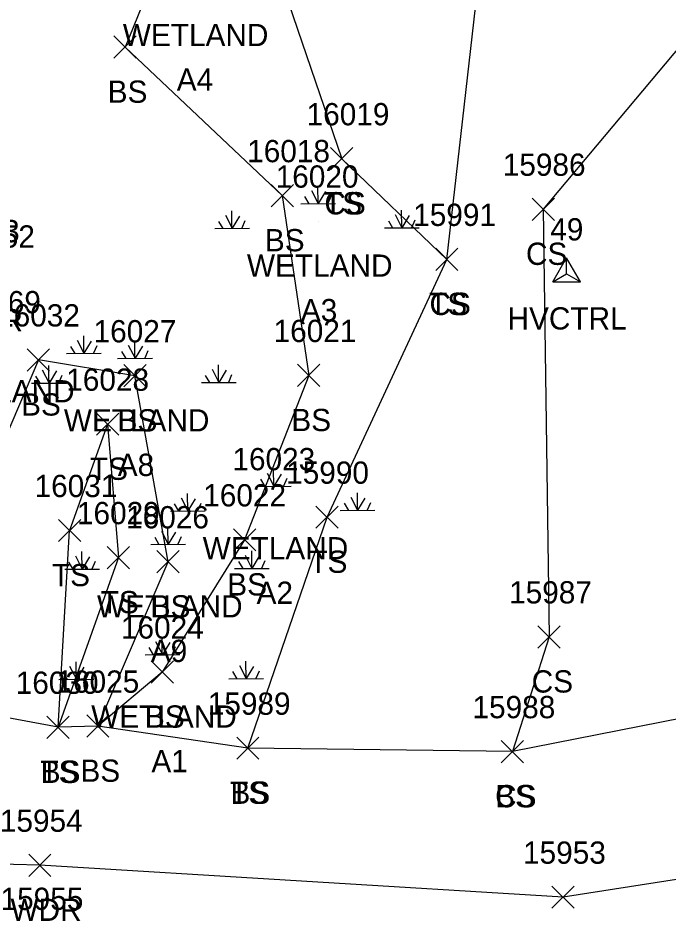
# Model space of a CAD drawing. Extents: x 1606530 to 1613020, y 784959 to 789666.
# Drawn here: x 1609329.8 to 1609388.2, y 788467.6 to 788548 of the extents above; entities that cross this region are included whole.
import ezdxf

# ---------------------------------------------------------------- set-up
doc = ezdxf.new("R2010")
doc.units = 0
for name, color, linetype in [('C_A', 7, 'Continuous'), ('C_I', 7, 'Continuous'), ('CPSM', 7, 'Continuous'), ('L_A', 7, 'Continuous'), ('L_C', 7, 'Continuous'), ('L_I', 7, 'Continuous'), ('L_TIC', 7, 'Continuous'), ('LAWA', 7, 'Continuous'), ('LELB', 7, 'Continuous'), ('LWET', 7, 'Continuous')]:
    doc.layers.add(name, color=color, linetype=linetype)

msp = doc.modelspace()

# ---------------------------------------------------------------- linework, layer by layer
at = {"layer": 'CPSM'}
for p, q in [((1609377.817, 788524.331), (1609379.067, 788526.496)), ((1609380.317, 788524.331), (1609379.067, 788526.496)), ((1609379.067, 788525.052), (1609379.067, 788526.496)), ((1609377.817, 788524.331), (1609379.067, 788525.052)), ((1609379.067, 788525.052), (1609379.067, 788525.052)), ((1609379.067, 788525.052), (1609380.317, 788524.331)), ((1609377.817, 788524.331), (1609380.317, 788524.331))]:
    msp.add_line(p, q, dxfattribs=at)
at = {"layer": 'L_TIC'}
for points in [[(1609338.409, 788544.413), (1609340.409, 788546.413)], [(1609340.409, 788544.413), (1609338.409, 788546.413)], [(1609357.873, 788534.391), (1609359.873, 788536.391)], [(1609359.873, 788534.391), (1609357.873, 788536.391)], [(1609357.873, 788534.391), (1609359.873, 788536.391)], [(1609359.873, 788534.391), (1609357.873, 788536.391)], [(1609352.526, 788531.076), (1609354.526, 788533.076)], [(1609354.526, 788531.076), (1609352.526, 788533.076)], [(1609375.975, 788529.856), (1609377.975, 788531.856)], [(1609377.975, 788529.856), (1609375.975, 788531.856)], [(1609367.309, 788525.354), (1609369.309, 788527.354)], [(1609369.309, 788525.354), (1609367.309, 788527.354)], [(1609367.309, 788525.354), (1609369.309, 788527.354)], [(1609369.309, 788525.354), (1609367.309, 788527.354)], [(1609330.632, 788516.324), (1609332.632, 788518.324)], [(1609332.632, 788516.324), (1609330.632, 788518.324)], [(1609339.298, 788514.898), (1609341.298, 788516.898)], [(1609341.298, 788514.898), (1609339.298, 788516.898)], [(1609354.901, 788514.928), (1609356.901, 788516.928)], [(1609356.901, 788514.928), (1609354.901, 788516.928)], [(1609336.843, 788510.551), (1609338.843, 788512.551)], [(1609338.843, 788510.551), (1609336.843, 788512.551)], [(1609336.843, 788510.551), (1609338.843, 788512.551)], [(1609338.843, 788510.551), (1609336.843, 788512.551)], [(1609356.552, 788502.201), (1609358.552, 788504.201)], [(1609358.552, 788502.201), (1609356.552, 788504.201)], [(1609333.433, 788501.004), (1609335.433, 788503.004)], [(1609335.433, 788501.004), (1609333.433, 788503.004)], [(1609333.433, 788501.004), (1609335.433, 788503.004)], [(1609335.433, 788501.004), (1609333.433, 788503.004)], [(1609349.146, 788500.166), (1609351.146, 788502.166)], [(1609351.146, 788500.166), (1609349.146, 788502.166)], [(1609337.811, 788498.568), (1609339.811, 788500.568)], [(1609339.811, 788498.568), (1609337.811, 788500.568)], [(1609342.274, 788498.194), (1609344.274, 788500.194)], [(1609344.274, 788498.194), (1609342.274, 788500.194)], [(1609376.491, 788491.451), (1609378.491, 788493.451)], [(1609378.491, 788491.451), (1609376.491, 788493.451)], [(1609341.753, 788488.296), (1609343.753, 788490.296)], [(1609343.753, 788488.296), (1609341.753, 788490.296)], [(1609332.393, 788483.335), (1609334.393, 788485.335)], [(1609334.393, 788483.335), (1609332.393, 788485.335)], [(1609332.393, 788483.335), (1609334.393, 788485.335)], [(1609334.393, 788483.335), (1609332.393, 788485.335)], [(1609335.962, 788483.436), (1609337.962, 788485.436)], [(1609337.962, 788483.436), (1609335.962, 788485.436)], [(1609335.962, 788483.436), (1609337.962, 788485.436)], [(1609337.962, 788483.436), (1609335.962, 788485.436)], [(1609349.434, 788481.457), (1609351.434, 788483.457)], [(1609351.434, 788481.457), (1609349.434, 788483.457)], [(1609349.434, 788481.457), (1609351.434, 788483.457)], [(1609351.434, 788481.457), (1609349.434, 788483.457)], [(1609373.203, 788481.146), (1609375.203, 788483.146)], [(1609375.203, 788481.146), (1609373.203, 788483.146)], [(1609373.203, 788481.146), (1609375.203, 788483.146)], [(1609375.203, 788481.146), (1609373.203, 788483.146)], [(1609330.758, 788470.946), (1609332.758, 788472.946)], [(1609332.758, 788470.946), (1609330.758, 788472.946)], [(1609377.742, 788468.077), (1609379.742, 788470.077)], [(1609379.742, 788468.077), (1609377.742, 788470.077)]]:
    msp.add_lwpolyline(points, dxfattribs=at)
at = {"layer": 'LAWA'}
msp.add_lwpolyline([(1609458.893, 788516.216), (1609465.518, 788489.735), (1609475.82, 788469.822), (1609458.93, 788473.776), (1609440.54, 788476.414), (1609422.319, 788472.182), (1609400.858, 788472.527), (1609378.742, 788469.077), (1609331.758, 788471.946), (1609305.698, 788472.619), (1609293.066, 788472.821), (1609275.811, 788471.772), (1609233.209, 788467.381), (1609185.699, 788461.65), (1609159.09, 788461.178), (1609160.3, 788482.227), (1609154.118, 788496.013), (1609177.082, 788505.785)], dxfattribs=at)
at = {"layer": 'LELB'}
for points in [[(1609366.827, 788579.614), (1609348.341, 788574.614), (1609345.128, 788559.502), (1609339.409, 788545.413), (1609353.526, 788532.076), (1609355.901, 788515.928), (1609350.146, 788501.166), (1609342.753, 788489.296), (1609336.962, 788484.436), (1609343.274, 788499.194), (1609340.298, 788515.898), (1609331.632, 788517.324), (1609323.809, 788499.051), (1609313.667, 788488.005), (1609309.548, 788485.41)], [(1609368.309, 788526.354), (1609371.613, 788555.314), (1609368.465, 788572.629), (1609352.942, 788568.099), (1609352.107, 788555.196), (1609358.873, 788535.391)], [(1609397.626, 788555.501), (1609376.975, 788530.856), (1609377.491, 788492.451), (1609374.203, 788482.146)], [(1609426.503, 788537.087), (1609427.324, 788507.853), (1609421.658, 788499.174), (1609408.568, 788488.921), (1609374.203, 788482.146), (1609350.434, 788482.457), (1609336.962, 788484.436), (1609333.393, 788484.335), (1609313.667, 788488.005)], [(1609350.434, 788482.457), (1609357.552, 788503.201), (1609368.309, 788526.354), (1609358.873, 788535.391)], [(1609337.843, 788511.551), (1609338.811, 788499.568), (1609333.393, 788484.335), (1609334.433, 788502.004)], [(1609337.843, 788511.551), (1609334.433, 788502.004)]]:
    msp.add_lwpolyline(points, dxfattribs=at)
at = {"layer": 'LWET'}
for p, q in [((1609356.144, 788532.54), (1609356.75, 788531.364)), ((1609356.74, 788531.355), (1609356.731, 788532.935)), ((1609355.537, 788531.989), (1609355.923, 788531.345)), ((1609357.412, 788532.448), (1609356.75, 788531.364)), ((1609357.908, 788532.044), (1609357.614, 788531.364)), ((1609355.188, 788531.345), (1609358.312, 788531.364)), ((1609348.416, 788530.318), (1609349.023, 788529.142)), ((1609349.013, 788529.133), (1609349.004, 788530.713)), ((1609349.684, 788530.226), (1609349.023, 788529.142)), ((1609363.662, 788530.375), (1609364.269, 788529.199)), ((1609364.259, 788529.19), (1609364.25, 788530.77)), ((1609364.93, 788530.284), (1609364.269, 788529.199)), ((1609347.81, 788529.767), (1609348.196, 788529.124)), ((1609350.18, 788529.822), (1609349.886, 788529.142)), ((1609356.74, 788529.792), (1609356.74, 788529.792)), ((1609363.056, 788529.824), (1609363.442, 788529.181)), ((1609364.309, 788529.251), (1609364.269, 788529.251)), ((1609365.426, 788529.879), (1609365.132, 788529.199)), ((1609347.461, 788529.124), (1609350.585, 788529.142)), ((1609349.063, 788529.194), (1609349.023, 788529.194)), ((1609362.707, 788529.181), (1609365.831, 788529.199)), ((1609335.109, 788519.093), (1609335.715, 788517.917)), ((1609335.706, 788517.908), (1609335.697, 788519.488)), ((1609336.377, 788519.001), (1609335.715, 788517.917)), ((1609340.298, 788517.46), (1609340.288, 788519.04)), ((1609334.503, 788518.542), (1609334.889, 788517.899)), ((1609336.873, 788518.597), (1609336.579, 788517.917)), ((1609339.094, 788518.094), (1609339.48, 788517.451)), ((1609339.701, 788518.645), (1609340.307, 788517.469)), ((1609340.969, 788518.553), (1609340.307, 788517.469)), ((1609341.465, 788518.149), (1609341.171, 788517.469)), ((1609334.154, 788517.899), (1609337.278, 788517.917)), ((1609335.756, 788517.969), (1609335.715, 788517.969)), ((1609338.745, 788517.451), (1609341.869, 788517.469)), ((1609331.973, 788516.424), (1609332.58, 788515.248)), ((1609332.57, 788515.238), (1609332.561, 788516.818)), ((1609347.219, 788516.481), (1609347.826, 788515.305)), ((1609347.816, 788515.295), (1609347.807, 788516.875)), ((1609348.487, 788516.389), (1609347.826, 788515.305)), ((1609331.367, 788515.872), (1609331.753, 788515.229)), ((1609333.241, 788516.332), (1609332.58, 788515.248)), ((1609333.738, 788515.928), (1609333.444, 788515.248)), ((1609340.298, 788515.898), (1609340.298, 788515.898)), ((1609346.613, 788515.929), (1609346.999, 788515.286)), ((1609348.984, 788515.985), (1609348.69, 788515.305)), ((1609331.018, 788515.229), (1609334.142, 788515.248)), ((1609332.621, 788515.3), (1609332.58, 788515.299)), ((1609346.264, 788515.286), (1609349.388, 788515.305)), ((1609347.867, 788515.357), (1609347.826, 788515.356)), ((1609352.765, 788505.976), (1609352.756, 788507.556)), ((1609352.168, 788507.162), (1609352.775, 788505.985)), ((1609353.436, 788507.07), (1609352.775, 788505.985)), ((1609351.213, 788505.967), (1609354.337, 788505.985)), ((1609351.562, 788506.61), (1609351.948, 788505.967)), ((1609353.933, 788506.665), (1609353.638, 788505.985)), ((1609345.038, 788503.755), (1609345.028, 788505.335)), ((1609360.284, 788503.812), (1609360.274, 788505.392)), ((1609343.834, 788504.389), (1609344.22, 788503.746)), ((1609344.441, 788504.94), (1609345.047, 788503.764)), ((1609345.709, 788504.848), (1609345.047, 788503.764)), ((1609346.205, 788504.444), (1609345.911, 788503.764)), ((1609352.765, 788504.414), (1609352.765, 788504.414)), ((1609359.08, 788504.446), (1609359.466, 788503.803)), ((1609359.687, 788504.997), (1609360.293, 788503.821)), ((1609360.955, 788504.905), (1609360.293, 788503.821)), ((1609361.451, 788504.501), (1609361.157, 788503.821)), ((1609343.485, 788503.746), (1609346.609, 788503.764)), ((1609345.088, 788503.816), (1609345.047, 788503.816)), ((1609358.731, 788503.803), (1609361.855, 788503.821)), ((1609360.334, 788503.873), (1609360.293, 788503.873)), ((1609342.677, 788501.942), (1609343.283, 788500.766)), ((1609343.273, 788500.757), (1609343.264, 788502.337)), ((1609342.07, 788501.391), (1609342.456, 788500.747)), ((1609343.945, 788501.85), (1609343.283, 788500.766)), ((1609344.441, 788501.446), (1609344.147, 788500.766)), ((1609341.721, 788500.747), (1609344.845, 788500.766)), ((1609334.949, 788499.72), (1609335.556, 788498.544)), ((1609335.546, 788498.535), (1609335.537, 788500.115)), ((1609336.217, 788499.628), (1609335.556, 788498.544)), ((1609350.195, 788499.777), (1609350.802, 788498.601)), ((1609350.792, 788498.592), (1609350.783, 788500.172)), ((1609351.463, 788499.686), (1609350.802, 788498.601)), ((1609334.343, 788499.169), (1609334.729, 788498.526)), ((1609336.714, 788499.224), (1609336.419, 788498.544)), ((1609343.274, 788499.194), (1609343.274, 788499.194)), ((1609349.589, 788499.226), (1609349.975, 788498.583)), ((1609351.959, 788499.281), (1609351.665, 788498.601)), ((1609333.994, 788498.526), (1609337.118, 788498.544)), ((1609335.597, 788498.596), (1609335.556, 788498.596)), ((1609349.24, 788498.583), (1609352.364, 788498.601)), ((1609350.843, 788498.653), (1609350.802, 788498.653)), ((1609342.753, 788490.858), (1609342.744, 788492.438)), ((1609341.55, 788491.492), (1609341.936, 788490.849)), ((1609342.156, 788492.044), (1609342.763, 788490.868)), ((1609343.424, 788491.952), (1609342.763, 788490.868)), ((1609343.921, 788491.548), (1609343.627, 788490.868)), ((1609341.201, 788490.849), (1609344.325, 788490.868)), ((1609334.429, 788489.822), (1609335.035, 788488.646)), ((1609335.026, 788488.637), (1609335.016, 788490.217)), ((1609349.675, 788489.879), (1609350.281, 788488.703)), ((1609350.272, 788488.694), (1609350.262, 788490.274)), ((1609333.823, 788489.271), (1609334.209, 788488.628)), ((1609335.697, 788489.73), (1609335.035, 788488.646)), ((1609336.193, 788489.326), (1609335.899, 788488.646)), ((1609342.753, 788489.296), (1609342.753, 788489.296)), ((1609349.069, 788489.328), (1609349.454, 788488.685)), ((1609350.943, 788489.787), (1609350.281, 788488.703)), ((1609351.439, 788489.383), (1609351.145, 788488.703)), ((1609333.474, 788488.628), (1609336.597, 788488.646)), ((1609335.076, 788488.698), (1609335.035, 788488.698)), ((1609348.719, 788488.685), (1609351.843, 788488.703)), ((1609350.322, 788488.755), (1609350.281, 788488.755))]:
    msp.add_line(p, q, dxfattribs=at)

# ---------------------------------------------------------------- texts
at = {"layer": 'C_A'}
msp.add_text('HVCTRL', height=2, dxfattribs=at).set_placement((1609373.76, 788520.052))
at = {"layer": 'C_I'}
msp.add_text('49', height=2, dxfattribs=at).set_placement((1609377.595, 788528.052))
at = {"layer": 'L_A'}
for s, p in [('WETLAND', (1609339.21, 788545.499)), ('BS', (1609337.85, 788540.413)), ('TS', (1609357.282, 788530.391)), ('CS', (1609357.314, 788530.391)), ('BS', (1609351.967, 788527.076)), ('CS', (1609375.416, 788525.856)), ('WETLAND', (1609350.355, 788524.792)), ('TS', (1609366.719, 788521.354)), ('CS', (1609366.75, 788521.354)), ('BRKR', (1609322.811, 788519.89)), ('WETLAND', (1609321.802, 788513.51)), ('BS', (1609330.073, 788512.324)), ('WETLAND', (1609333.912, 788510.898)), ('BS', (1609338.739, 788510.898)), ('BS', (1609354.342, 788510.928)), ('TS', (1609336.253, 788506.551)), ('TS', (1609336.253, 788506.551)), ('WETLAND', (1609346.38, 788499.414)), ('TS', (1609355.962, 788498.201)), ('TS', (1609332.842, 788497.004)), ('TS', (1609332.842, 788497.004)), ('BS', (1609348.587, 788496.166)), ('TS', (1609337.221, 788494.568)), ('WETLAND', (1609336.888, 788494.194)), ('BS', (1609341.715, 788494.194)), ('CS', (1609375.932, 788487.451)), ('WETLAND', (1609336.368, 788484.296)), ('BS', (1609341.194, 788484.296)), ('TS', (1609331.802, 788479.335)), ('BS', (1609331.834, 788479.335)), ('BS', (1609335.403, 788479.436)), ('BS', (1609335.403, 788479.436)), ('TS', (1609348.844, 788477.457)), ('BS', (1609348.875, 788477.457)), ('CS', (1609372.644, 788477.146)), ('BS', (1609372.644, 788477.146)), ('WDR', (1609329.12, 788466.946))]:
    msp.add_text(s, height=2, dxfattribs=at).set_placement(p)
at = {"layer": 'L_C'}
for s, p in [('A4', (1609344.052, 788541.499)), ('A3', (1609355.197, 788520.792)), ('A8', (1609338.754, 788506.898)), ('A2', (1609351.222, 788495.414)), ('A9', (1609341.723, 788490.194)), ('A1', (1609341.777, 788480.296))]:
    msp.add_text(s, height=2, dxfattribs=at).set_placement(p)
at = {"layer": 'L_I'}
for s, p in [('16019', (1609355.716, 788538.391)), ('16019', (1609355.716, 788538.391)), ('16018', (1609350.377, 788535.076)), ('15986', (1609373.33, 788533.856)), ('16020', (1609352.938, 788532.792)), ('15991', (1609365.286, 788529.354)), ('15991', (1609365.286, 788529.354)), ('16053', (1609322.504, 788527.89)), ('16052', (1609323.875, 788527.41)), ('16069', (1609324.416, 788521.51)), ('16032', (1609327.916, 788520.324)), ('16027', (1609336.581, 788518.898)), ('16027', (1609336.581, 788518.898)), ('16021', (1609352.752, 788518.928)), ('16028', (1609334.127, 788514.551)), ('16028', (1609334.127, 788514.551)), ('16023', (1609349.049, 788507.414)), ('15990', (1609353.876, 788506.201)), ('16031', (1609331.284, 788505.004)), ('16031', (1609331.284, 788505.004)), ('16022', (1609346.429, 788504.166)), ('16029', (1609335.087, 788502.568)), ('16026', (1609339.502, 788502.194)), ('16026', (1609339.502, 788502.194)), ('15987', (1609373.901, 788495.451)), ('16024', (1609339.037, 788492.296)), ('16024', (1609339.037, 788492.296)), ('16030', (1609329.59, 788487.335)), ('16030', (1609329.59, 788487.335)), ('16025', (1609333.246, 788487.436)), ('16025', (1609333.246, 788487.436)), ('15989', (1609346.836, 788485.457)), ('15989', (1609346.836, 788485.457)), ('15988', (1609370.612, 788485.146)), ('15988', (1609370.612, 788485.146)), ('15954', (1609328.168, 788474.946)), ('15953', (1609375.151, 788472.077)), ('15955', (1609328.229, 788467.93))]:
    msp.add_text(s, height=2, dxfattribs=at).set_placement(p)

doc.saveas('drawing.dxf')
